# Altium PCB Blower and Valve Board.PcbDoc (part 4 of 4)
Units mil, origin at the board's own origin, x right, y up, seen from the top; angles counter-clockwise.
Board outline 4950 x 3450 mil, 4 copper layers (Top Layer, Signal Layer 1, Signal Layer 2, Bottom Layer), stack 64.4 mil thick; 260 components, 151 nets, 912 pads, 417 vias.
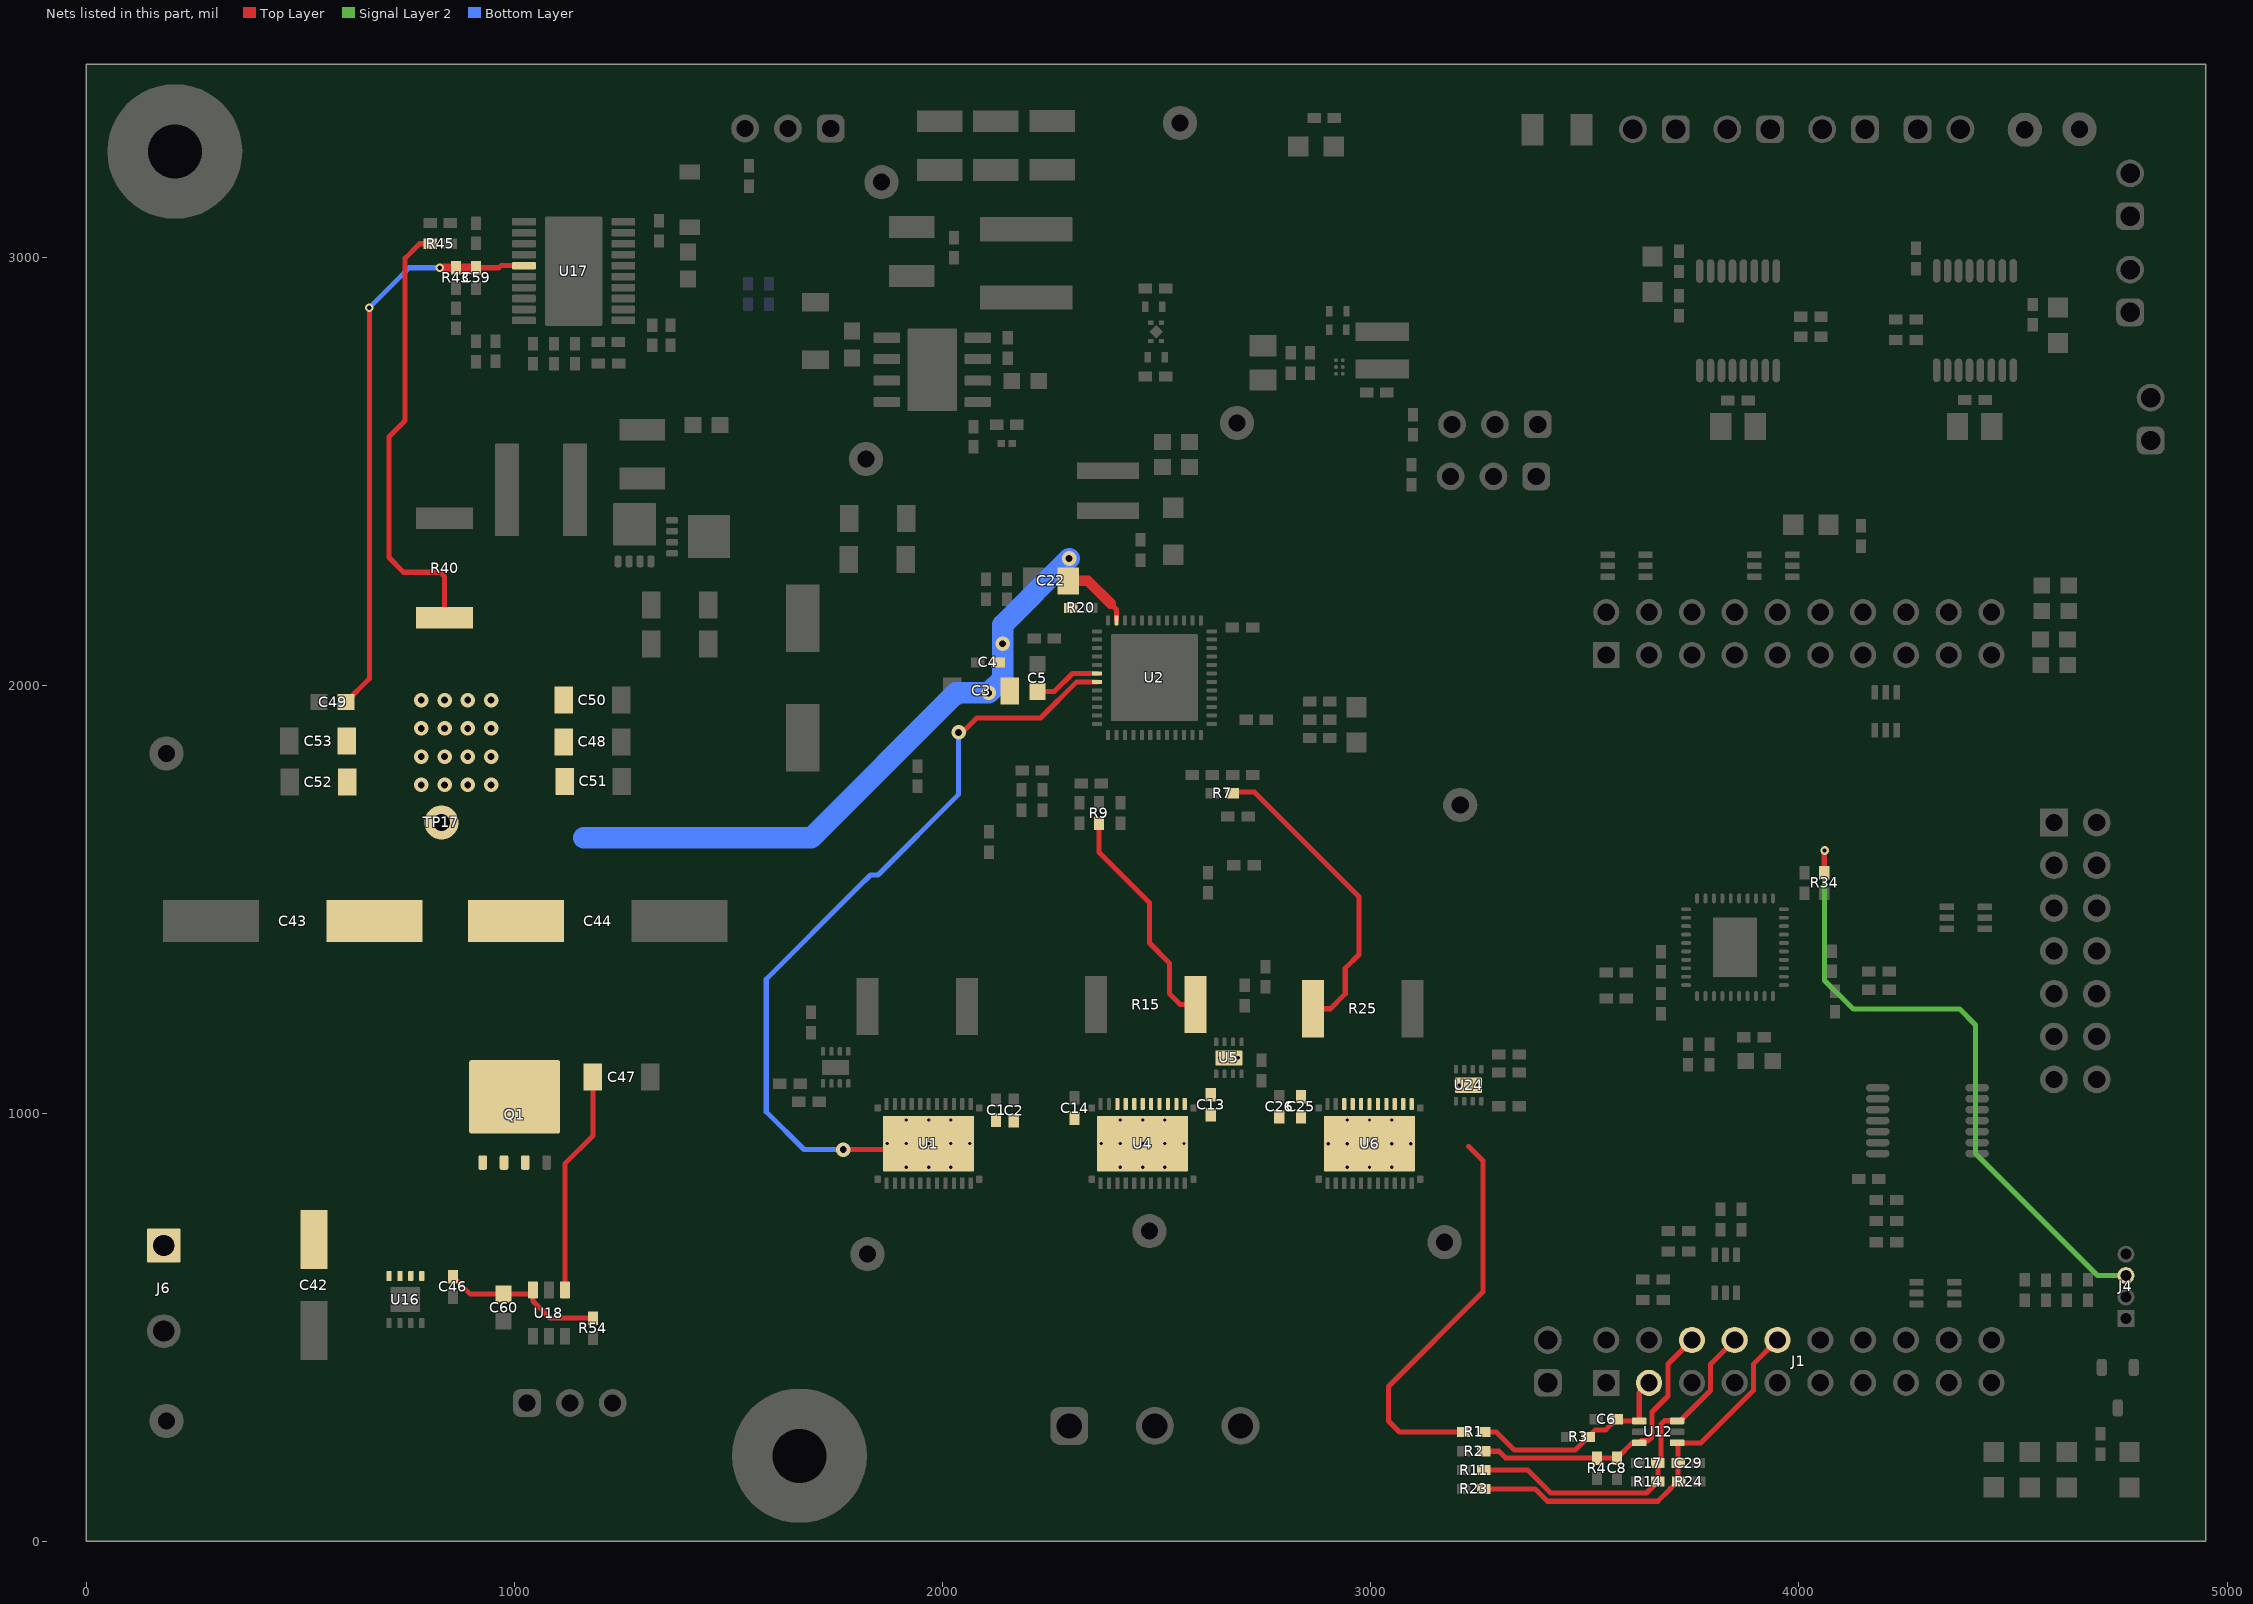
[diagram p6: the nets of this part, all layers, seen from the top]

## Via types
v1: diameter 34, hole 16, Top Layer to Bottom Layer, 186 vias
v2: diameter 20, hole 10, Top Layer to Bottom Layer, 125 vias
v3: diameter 19.68, hole 7.87, Top Layer to Bottom Layer, 94 vias
v4: diameter 19.68, hole 7.87, Top Layer to Bottom Layer, tented both sides, 12 vias

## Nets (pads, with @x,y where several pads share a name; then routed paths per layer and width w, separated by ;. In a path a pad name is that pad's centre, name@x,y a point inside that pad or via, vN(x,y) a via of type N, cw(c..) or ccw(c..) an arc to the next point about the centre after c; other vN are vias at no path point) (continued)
SPB1: C13.2 R9.1 R15.2 U4.12 U4.13 U4.14 U4.15 U4.16 U4.17 U4.18 U4.19 U4.20 U5.9@2668.47,1129.31 | length 538
  Top Layer w12: R9.1@2364.96,1677.65 2364.96,1609.77 2373.86,1600.88 2482.92,1491.81 2482.92,1397.63 2529.53,1351.03 2529.53,1279.7 2555.12,1254.11 R15.2@2590.8,1254.11
  other v3: 2646.82,1129.31 2690.13,1129.31
SPC1: C25.2 R7.1 R25.2 U6.12 U6.13 U6.14 U6.15 U6.16 U6.17 U6.18 U6.19 U6.20 U24.9@3228.35,1065.55 | length 726.8
  Top Layer w12: R7.1@2677.1,1750.51 2727.84,1750.51 2972.44,1505.91 2972.44,1370.71 2940.51,1338.78 2940.51,1279.09 2905.69,1244.27 R25.2@2864.81,1244.27
  other v3: 3206.69,1065.55 3250,1065.55
TXD: J4.3 R34.2 | length 1521
  Top Layer w12: R34.2@4059.11,1561.62 4059.11,1612.89 v2(4060,1613.78)
  Signal Layer 2 w12: v2(4060,1613.78) 4060,1310.41 4127.1,1243.31 4375.45,1243.31 4412.51,1206.25 4412.51,906.16 4697.71,620.97 J4.3@4763.78,620.97
VDRAIN: C1.1 C2.1 C3.1 C4.1 C5.1 C13.1 C14.1 C22.1 C25.1 C26.1 C43.1 C44.1 C47.1 C48.1 C49.1 C50.1 C51.1 C52.1 C53.1 C59.1 Q1.5 Q1.6 Q1.7 Q1.8 Q1.9@1000.49,1038.58 R1.2 R20.2 R40.1 R43.2 R45.2 TP17.1 U1.27 U2.6 U2.7 U2.47 U4.27 U6.27 U17.5 U18.4 | length 7512.7
  Top Layer w12: C49.1@606.78,1960.63 661.01,2014.86 v2(661.01,2881.67) ; R45.2@803.19,3031.03 778.37,3031.03 744.59,2997.25 744.59,2618.11 706.69,2580.22 706.69,2297.93 740.85,2263.78 826.77,2263.78 836.61,2253.94 R40.1@836.61,2157.48 ; C59.1@910.25,2974.84 963.1,2974.84 968.1,2979.85 U17.5@1022.14,2979.85 ; U18.4@1117.64,587.63 1117.64,882.14 1183.07,947.58 C47.1@1183.07,1084.65 ; v1(1767.72,915.35) 1915.21,915.35 1953.22,915.35 v3(1967.18,929.31) ; v1(2037.44,1889.76) 2046.17,1889.76 2079.54,1923.13 2228.49,1923.13 2313.07,2007.71 U2.7@2360.88,2007.71 ; C5.1@2221.11,1985.01 2260.83,1985.01 2303.21,2027.4 U2.6@2360.88,2027.4 ; 2392.37,2190.52 2406.15,2176.74 U2.47@2406.15,2151.41 ; R1.2@3217.13,255.87 3066.78,255.87 3041.34,281.3 3041.34,362.17 3262.41,583.24 3262.41,889.02 3228.94,922.49
  Top Layer w20: v2(825.29,2974.84) R43.2@863.01,2974.84 C59.1@910.25,2974.84
  Top Layer w25: C22.1@2292.96,2243.67 2339.22,2243.67 2392.37,2190.52
  Bottom Layer w12: v2(661.01,2881.67) 754.19,2974.84 v2(825.29,2974.84) ; v1(1767.72,915.35) 1676.32,915.35 1587.96,1003.72 1587.96,1313.18 1800.71,1525.93 1800.71,1526.06 1818.28,1543.63 1818.41,1543.63 1831.52,1556.74 1849.07,1556.74 2037.4,1745.08 2037.4,1881.58 2037.44,1881.62 v1(2037.44,1889.76)
  Bottom Layer w50: 1161.42,1643.7 1693.56,1643.7 2031.92,1982.06 v1(2107.88,1982.06) 2140.16,2014.34 v1(2140.16,2096.67) 2140.16,2140.69 v1(2295.32,2295.85)
  other v1: 782.28,1766.99 836.61,1766.99 890.95,1766.99 945.28,1766.99 782.28,1833.04 836.61,1833.04 890.95,1833.04 945.28,1833.04 782.28,1899.1 836.61,1899.1 890.95,1899.1 945.28,1899.1 782.28,1965.15 836.61,1965.15 890.95,1965.15 945.28,1965.15
  other v3: 1915.21,874.19 1967.18,874.19 2019.14,874.19 2415.21,874.19 2467.18,874.19 2519.14,874.19 2945.08,873.99 2997.05,873.99 3049.02,873.99 1870.72,929.31 1915.21,929.31 2019.14,929.31 2063.63,929.31 2370.72,929.31 2415.21,929.31 2467.18,929.31 2519.14,929.31 2563.63,929.31 2900.59,929.11 2945.08,929.11 2997.05,929.11 3049.02,929.11 3093.51,929.11 1915.21,984.42 1967.18,984.42 2019.14,984.42 2415.21,984.42 2467.18,984.42 2519.14,984.42 2945.08,984.23 2997.05,984.23 3049.02,984.23
VIN: C42.1 C46.1 C60.1 J6.1 Q1.1 Q1.2 Q1.3 R54.2 U16.1 U16.2 U16.3 U16.4 U18.6 | length 390.4
  Top Layer w12: C46.1@856.3,618.11 896.82,577.59 C60.1@974.41,577.59 1032.8,577.59 U18.6@1042.83,587.63 1042.83,561.58 1082.7,521.72 R54.2@1183.21,521.72
VSENA: C8.1 J1.6 R2.1 R4.2 U12.3 | length 684.6
  Top Layer w12: R2.1@3264.37,210.6 3299.24,210.6 3315.15,194.69 R4.2@3528.35,194.69 C8.1@3575,194.69 3610.63,230.32 U12.3@3626.97,230.32 3631.69,235.03 3647.93,235.03 3656.7,243.8 3656.7,302.07 3694.29,339.66 3694.29,414.76 J1.6@3750,470.47
VSENB: C17.1 J1.8 R11.1 R14.2 U12.6 | length 866.4
  Top Layer w12: R11.1@3264.37,166.62 3366.85,166.62 3420.33,113.14 3643.94,113.14 R14.2@3670.75,139.95 C17.1@3670.75,182.88 3677.81,189.94 3677.81,273.77 3685.95,281.91 3715.14,281.91 U12.6@3715.55,281.5 3722.56,281.5 3793.51,352.45 3793.51,413.98 J1.8@3850,470.47
VSENC: C29.1 J1.10 R23.1 R24.2 U12.4 | length 945.1
  Top Layer w12: R23.1@3264.37,122.63 3383.96,122.63 3412.87,93.73 3670.47,93.73 3699.5,122.75 3699.5,123.07 3717.76,141.33 C29.1@3717.76,182.88 3717.76,228.11 U12.4@3715.55,230.32 3771.38,230.32 3893.51,352.45 3893.51,413.98 J1.10@3950,470.47
VSENVM: C6.1 J1.3 R1.1 R3.2 U12.1 | length 509.9
  Top Layer w12: R1.1@3264.37,255.87 3293.14,255.87 3335.31,213.69 3477.47,213.69 R3.2@3507.87,244.09 3524.4,260.62 3548.81,260.62 C6.1@3573.62,285.43 3577.56,281.5 U12.1@3626.97,281.5 3626.97,347.44 J1.3@3650,370.47
pads on no net: H7.0 H8.0 J1.2 J1.5 J1.7 J1.11 J1.17 J1.18 J1.19 J1.20 J2.4 J2.6 J2.8 J2.10 J2.13 J2.16 J3.2 J3.3 J3.5 J3.6 J3.8 J3.10 J3.11 J3.12 J3.13 J3.14 Q1.9@907.08,963.39 Q1.9@948.12,975 Q1.9@948.12,1020.28 Q1.9@948.12,1065.55 Q1.9@1000.49,975 Q1.9@1000.49,1020.28 Q1.9@1000.49,1025.59 Q1.9@1000.49,1065.55 Q1.9@1052.85,975 Q1.9@1052.85,1020.28 Q1.9@1052.85,1065.55 Q1.9@1093.89,963.39 Q2.9A Q2.9B Q2.9C Q2.9D Q3.9A Q3.9B Q3.9C Q3.9D U1. U1.21 U1.23 U1.24 U1.25 U1.26 U3.9@1732.28,1107.09 U3.9@1767.72,1107.09 U4. U4.21 U4.23 U4.24 U4.25 U4.26 U5.9@2650.76,1129.31 U5.9@2686.19,1129.31 U6. U6.21 U6.23 U6.24 U6.25 U6.26 U7.3 U7.6 U7.11 U8.2 U8.13 U8.14 U8.19 U8.20 U8.29 U8.30 U8.31 U8.32 U8.35 U8.36 U8.37 U8.38 U9.5 U10.3 U10.4 U10.5 U11.5 U12.5 U13.3 U13.4 U13.5 U14.1 U14.5 U15.5 U17.1 U17.21@1138.29,2967.06 U19.4 U24.9@3210.63,1065.55 U24.9@3246.06,1065.55

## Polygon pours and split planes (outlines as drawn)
GND on Top Layer "TOP_LAYER_GND_P129" (solid, remove dead copper, pour order 129): 59.06,3405.51 49.21,3395.67 49.21,49.21 59.06,39.37 4881.73,39.37 4891.73,49.37 4891.73,3395.67 4881.89,3405.51
GND on Top Layer "TOP_LAYER_GND_P127" (solid, remove dead copper, pour order 127): 3900.94,1185.4 3894.44,1178.91 3894.44,1163.63 3917.32,1140.75 3917.32,1088.5 3972.36,1033.46 4035.43,1033.46 4045.28,1043.31 4045.28,1140.93 4000.8,1185.4
3.3V on Top Layer "TOP_LAYER_3.3V_P125" (solid, remove dead copper, pour order 125): 3887.13,1039.29 3906.87,1059.03 3906.87,1144.05 3894.44,1156.48 3894.44,1184.1 3879.91,1198.63 3858.81,1198.63 3832.16,1171.98 3832.16,1152.32 3853.95,1130.52 3853.95,1052.85 3867.52,1039.29
GND on Top Layer "TOP_LAYER_GND_P123" (solid, remove dead copper, pour order 123): 1480.31,2976.22 1469.8,2986.74 1450.99,2986.74 1436.69,2972.44 1352.7,2972.44 1342.18,2961.92 1342.18,2927.75 1407.08,2862.84 1462.91,2862.84 1480.32,2880.25
NetC41_2 on Top Layer "TOP_LAYER_NETC41_2_P121" (solid, remove dead copper, pour order 121): 1205.18,2623.05 1205.18,2589.82 1249,2546.01 1420.41,2546.01 1437.01,2562.6 1437.01,2635.7 1420.8,2651.91 1235.11,2651.91
NetC64_1 on Top Layer "TOP_LAYER_NETC64_1_P117" (solid, remove dead copper, pour order 117): 1073.43,2322.82 1075.67,2320.58 1384.5,2320.58 1387.8,2323.88 1387.8,2483.98 1342.25,2529.53 1241.31,2529.53 1174.17,2596.66 1076.93,2596.66 1073.43,2593.16
NetL2_1 on Top Layer "TOP_LAYER_NETL2_1_P115" (solid, remove dead copper, pour order 115): 769.88,2322.83 1050.01,2322.83 1053.15,2325.98 1053.15,2580.22 1044,2589.37 886.61,2589.37 759.84,2462.6 759.84,2331.56
12V on Top Layer "TOP_LAYER_12V_P113" (solid, remove dead copper, pour order 113): 3850.63,2658.2 3831.67,2677.17 3785,2677.17 3731.83,2624 3731.83,2557.54 3759.84,2529.53 3832.66,2529.53 3850.63,2547.5
12V on Top Layer "TOP_LAYER_12V_P111" (solid, remove dead copper, pour order 111): 4403.17,2648.06 4386.23,2665 4315.1,2665 4277.26,2627.16 4277.26,2561.29 4304.5,2534.04 4383.55,2534.04 4403.17,2553.66
3.3V on Top Layer "TOP_LAYER_3.3V_P081" (solid, remove dead copper, pour order 81): 3089.76,2781.74 2957.56,2781.74 2923.23,2816.07 2923.69,2816.54 2923.69,2928.78 2947.67,2952.76 3088.89,2952.76 3123.11,2918.54 3123.11,2814.96
VIN on Top Layer "TOP_LAYER_VIN_P105" (solid, remove dead copper, pour order 105): 1027.12,920.9 62.66,920.9 39.37,897.61 39.37,629.92 66.93,602.36 938.3,602.36 1043.39,707.46 1043.39,905.56
LDO3.3 on Top Layer "TOP_LAYER_LDO3.3_P085" (solid, remove dead copper, pour order 85): 2493.19,2858.45 2517.24,2834.41 2563.68,2834.41 2608.27,2879 2608.27,2947.99 2573.98,2982.28 2506.13,2982.28 2498.82,2974.98 2498.82,2903.27 2493.19,2897.64
4.0V on Top Layer "TOP_LAYER_4.0V_P079" (solid, remove dead copper, pour order 79): 2312.99,2460.63 2535.6,2460.63 2541.94,2466.97 2541.94,2599.79 2562.23,2620.08 2801.72,2620.08 2885.39,2703.75 2885.39,2736.23 2875.56,2746.06 2702.71,2746.06 2554.37,2746.06 2516.16,2784.27 2504.64,2784.27 2504.64,2688.06 2415,2598.43 2312.99,2598.43 2293.31,2578.74 2293.76,2578.29 2293.76,2480.32
NetC21_2 on Top Layer "TOP_LAYER_NETC21_2_P077" (solid, remove dead copper, pour order 77): 2474.39,2315.77 2487.04,2328.42 2487.04,2349.4 2500.85,2363.21 2559.04,2363.21 2576.16,2380.33 2576.16,2449.47 2569.33,2456.3 2308.16,2456.3 2290.18,2438.31 2290.18,2372.94 2314.12,2348.99 2399.91,2348.99 2433.13,2315.77
VDRAIN on Top Layer "TOP_LAYER_VDRAIN_P073" (solid, remove dead copper, pour order 73): 2259.14,2164.2 2322.83,2164.2 2322.83,2192.07 2332.68,2201.92 2358.18,2201.92 2359.33,2200.76 2372.05,2213.48 2372.05,2283.46 2334.89,2320.62 2263.48,2320.62 2249.36,2306.5 2249.36,2218.81 2249.36,2171.08
VDRAIN on Top Layer "TOP_LAYER_VDRAIN_P071" (solid, remove dead copper, pour order 71): 2086.61,1947.29 2226.08,1947.29 2248.45,1969.65 2248.45,2007.87 2239.81,2016.51 2199.13,2016.51 2193.85,2021.79 2193.85,2086.21 2162.76,2117.29 2128.75,2117.29 2105.79,2094.33 2105.79,2041.2 2086.61,2022.02
SPA1 on Top Layer "TOP_LAYER_SPA1_P067" (solid, remove dead copper, pour order 67): 2096.46,1000.43 2103.25,1007.23 2139.76,1007.23 2146.31,1013.78 2146.31,1066.3 2097.75,1114.86 1978.42,1114.86 1929.13,1164.15 1929.13,1334.41 1918.54,1345 1792.4,1345 1771.65,1324.26 1771.65,1171.63 1777.27,1166.01 1796.58,1166.01 1801.18,1161.42 1801.02,1129.31 1714.57,1129.31 1714.57,1085.43 1800.95,1085.43 1811.02,1075.36 1811.02,1014.4 1824.99,1000.43
VDRAIN on Top Layer "TOP_LAYER_VDRAIN_P063" (solid, remove dead copper, pour order 63): 1801.18,960.8 1801.18,976.55 1833.26,1008.63 3206.14,1010.57 3238.19,978.52 3238.19,890.72 3203.76,856.3 1814.96,856.3 1801.18,870.08
SPC1 on Top Layer "TOP_LAYER_SPC1_P059" (solid, remove dead copper, pour order 59): 3132.53,1000.43 2863.25,1000.43 2848.55,1015.13 2821.46,1015.13 2795.28,1041.31 2795.28,1317.15 2853.99,1375.86 2952.76,1375.86 2966.39,1362.23 2966.39,1216.07 3093.5,1088.95 3265.75,1088.95 3265.75,1044.86 3145.72,1044.86 3132.53,1031.67
SPB1 on Top Layer "TOP_LAYER_SPB1_P055" (solid, remove dead copper, pour order 55): 2332.68,1000.43 2585.15,1000.43 2604.58,1019.86 2638.33,1019.86 2647.88,1029.41 2647.88,1058.98 2633.44,1073.43 2618.11,1073.43 2618.11,1106.89 2703.91,1107.09 2703.91,1150.96 2703.29,1151.57 2633.44,1151.57 2633.44,1314.22 2602.66,1345 2487.83,1345 2460.63,1317.8 2460.63,1155.64 2365.24,1060.25 2349.44,1060.25 2332.68,1043.48
no net on Top Layer "TOP_LAYER_NONET_P053" (solid, remove dead copper, pour order 53): 2545.13,1096.46
MOTC on Top Layer "TOP_LAYER_MOTC_P045" (solid, remove dead copper, pour order 45): 2676.6,846.04 2687.01,856.3 3228.35,856.3 3238.19,846.46 3238.19,590.55 2842.33,194.69 2606.07,194.69 2588.58,212.18 2588.58,650.69 2676.6,738.7
MOTA on Top Layer "TOP_LAYER_MOTA_P041" (solid, remove dead copper, pour order 41): 1801.02,856.3 2233.74,856.3 2244.09,845.95 2244.09,797.24 2391.73,649.61 2391.73,210.02 2376.4,194.69 2155.74,194.69 1761.81,588.26 1761.81,832.93
MOTB on Top Layer "TOP_LAYER_MOTB_P039" (solid, remove dead copper, pour order 39): 2657.48,856.3 2666.51,847.27 2666.51,738.7 2578.74,650.93 2578.74,211.17 2562.25,194.69 2420.69,194.69 2403.2,212.18 2403.2,652.89 2251.46,804.63 2251.46,849.24 2258.51,856.3
12V on Top Layer "TOP_LAYER_12V_P035" (solid, remove dead copper, pour order 35): 2312.99,3030.53 1860.24,3030.53 1838.32,3052.45 1838.32,3220.21 1866.14,3248.03 2312.99,3248.03 2342.52,3218.5 2342.52,3061.02
NetC69_2 on Top Layer "TOP_LAYER_NETC69_2_P033" (solid, remove dead copper, pour order 33): 2045.92,2790.14 2235.79,2790.14 2317.7,2872.05 2317.29,2872.45 2317.29,2936.08 2307.73,2945.65 2078.18,2945.65 2045.92,2913.39
14V on Top Layer "TOP_LAYER_14V_P031" (solid, remove dead copper, pour order 31): 1405.39,2409.63 1409.35,2413.59 1456.49,2460.74 1456.49,2630.89 1613.3,2787.7 1901.63,2787.7 1909.45,2779.88 1909.45,2747.93 1899.61,2738.08 1820.8,2738.08 1787.96,2705.25 1787.96,2588.88 1830.84,2546.01 1830.84,2089.96 1787.96,2047.08 1425.76,2047.08 1405.39,2067.45
VDRAIN on Top Layer "TOP_LAYER_VDRAIN_P023" (solid, remove dead copper, pour order 23): 1082.03,934.85 827.78,934.85 542.16,1220.47 542.16,1654.37 580.71,1692.91 580.71,2031.61 763.67,2214.57 924.89,2214.57 1151.57,1987.88 1151.57,1199.19 1214.57,1136.2 1214.57,1014.85 1134.76,935.04
GND on Bottom Layer "BOTTOM_LAYER_GND_P135" (solid, remove dead copper, pour order 135): 59.06,3405.51 49.21,3395.67 49.21,49.21 59.06,39.37 4881.73,39.37 4891.73,49.37 4891.73,3395.67 4881.89,3405.51
12V on Bottom Layer "BOTTOM_LAYER_12V_P109" (solid, remove dead copper, pour order 109): 1866.9,3248.03 1839.08,3220.21 1838.32,3220.21 1838.32,3055.51 1859.51,3034.32 3028.93,3034.32 3563.2,2500.05 4569.5,2500.05 4605.3,2535.86 4605.3,2674.42 4560.97,2718.74 3773.03,2718.74 3243.74,3248.03 2514.1,3248.03
VDRAIN on Bottom Layer "BOTTOM_LAYER_VDRAIN_P089" (solid, remove dead copper, pour order 89): 523.39,2232.8 475.23,2184.64 475.23,973.11 1109.91,338.43 3161.83,338.43 3239.1,415.7 3239.1,943.95 3146.27,1036.78 1719.41,1036.78 1249.1,1507.08 1249.1,2089.45 1105.75,2232.8
GND on Signal Layer 1 "SIGNAL_LAYER_1_GND_P131" (solid, remove dead copper, pour order 131): 59.06,3405.51 49.21,3395.67 49.21,49.21 59.06,39.37 4881.73,39.37 4891.73,49.37 4891.73,3395.67 4881.89,3405.51
GND on Signal Layer 2 "SIGNAL_LAYER_2_GND_P133" (solid, remove dead copper, pour order 133): 59.06,3405.51 49.21,3395.67 49.21,49.21 59.06,39.37 4881.73,39.37 4891.73,49.37 4891.73,3395.67 4881.89,3405.51

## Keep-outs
Keep-Out Layer:
  text ".Layer_Name" at 577,-858.49 h60

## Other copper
Top Layer:
  text ".Layer_Name" at 577,-858.49 h60
Bottom Layer:
  text ".Layer_Name" at 577,-858.49 h60

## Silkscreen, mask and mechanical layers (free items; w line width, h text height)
Top Overlay:
  text "EN: 2-3" at 1523.68,3375.07 h40
  text ".PRJ_Number" at 472.44,2699.17 h90 r270
  text "REV: .PCB_Rev" at 364.17,2679.54 h72.83 r270
  text "EN: 2-3" at 1131.89,226.38 h40
  text "D11 = Alert 3 / D6 = Alert 1 / D7 = Alert 2 / D8 = MCUON" at 4131.4,100.98 h40
  text ".Layer_Name" at 577,-858.49 h60
Bottom Overlay:
  text ".Layer_Name" at 577,-858.49 h60
Top Paste:
  text ".Layer_Name" at 577,-858.49 h60
Bottom Paste:
  text ".Layer_Name" at 577,-858.49 h60
Top Solder:
  text ".Layer_Name" at 577,-858.49 h60
  text ".Layer_Name" at 577,-858.49 h60
Bottom Solder:
  text ".Layer_Name" at 577,-858.49 h60
Drill Guide:
  text ".Layer_Name" at 577,-858.49 h60
M1 Board Outline:
  the board outline again, w10
  text ".Layer_Name" at 577,-858.49 h60
M2 Board Dimensions:
  rectangle: 0,-275 125,-150
  rectangle: 125,-400 500,-275
  lines w7: 0,-275 1000,-275 ; 125,-400 125,-150 ; 250,-400 250,-150 ; 500,-400 500,-150 ; 750,-400 750,-150 ; 0,-400 1000,-400 1000,-150 0,-150 0,-400
  text ".Layer_Name" at 577,-858.49 h60
M3 3D STEP Top:
  text ".Layer_Name" at 577,-858.49 h60
M4 3D STEP Bottom:
  text ".Layer_Name" at 577,-858.49 h60
M5 Assembly Top:
  lines w10: -292,-930.17 6308,-930.17 ; -292,-726.83 6310,-726.83 ; -292,-523.5 -292,-1133.5 3713,-1133.5 6310,-1133.5 6310,-523.5 -291.5,-523.5 -291.5,-1133.5 1284,-1133.5 ; 2173,-1133.5 2173,-523.5 ; 3440,-726.83 3440,-523.5 ; 4280,-726.83 4280,-523.5 ; 4902,-1140 4902,-937.17
  text "COMPONENTS MARKED 'DNP' SHOULD NOT BE POPULATED." at 1153.5,-318.5 h60
  text "ASSEMBLY VARIANT:" at 1153,-434 h60
  text ".VariantName" at 2189,-434 h60
  text "PCB VIEWED FROM TOP SIDE" at -228.5,-655.67 h60
  text "BOARD #:" at 2248,-655.67 h60
  text ".PRJ_Number" at 2793.5,-655.67 h60
  text "REV:" at 3638,-655.67 h60
  text ".PCB_Rev" at 3929.5,-655.67 h60
  text "SVN REV:" at 4476,-655.67 h60
  text ".VersionControl_RevNumber" at 4982,-655.67 h60
  text "TID #:" at 2248,-859 h60
  text ".TID" at 2793.5,-859 h60
  text "PLOT NAME =" at -228.5,-1064.34 h60
  text ".plot_File_Name" at 577,-1064.34 h60
  text "GENERATED    :" at 2250,-1064.34 h60
  text ".Print_Date" at 3119.5,-1064.34 h60
  text ".Print_Time" at 3848.5,-1064.34 h60
  text "TEXAS INSTRUMENTS" at 5113,-1064.34 h60
M6 Assembly Bottom:
  lines w10: -292.5,-727.33 6309.5,-727.33 ; -290.5,-930.67 6309.5,-930.67 ; 1115.5,-1140.5 1115.5,-937.67 ; 1737.5,-727.33 1737.5,-524 ; 2577.5,-727.33 2577.5,-524 ; 3844.5,-1134 3844.5,-524 ; 4733.5,-1134 6309,-1134 6309,-524 -292.5,-524 -292.5,-1134 2304.5,-1134 6309.5,-1134 6309.5,-524
  text "COMPONENTS MARKED 'DNP' SHOULD NOT BE POPULATED." at 6102,-318 h60
  text ".VariantName" at 5058,-434 h60
  text "ASSEMBLY VARIANT:" at 6097,-434 h60
  text ".VersionControl_RevNumber" at 1035.5,-656.17 h60
  text "SVN REV:" at 1541.5,-656.17 h60
  text ".PCB_Rev" at 2088,-656.17 h60
  text "REV:" at 2379.5,-656.17 h60
  text ".PRJ_Number" at 3224,-656.17 h60
  text "BOARD #:" at 3769.5,-656.17 h60
  text "PCB VIEWED FROM BOTTOM SIDE" at 6246,-656.17 h60
  text ".TID" at 3224,-859.5 h60
  text "TID #:" at 3769.5,-859.5 h60
  text "TEXAS INSTRUMENTS" at 904.5,-1064.84 h60
  text ".Print_Time" at 2169,-1064.84 h60
  text ".Print_Date" at 2898,-1064.84 h60
  text "GENERATED    :" at 3767.5,-1064.84 h60
  text ".plot_File_Name" at 5440.5,-1064.84 h60
  text "PLOT NAME =" at 6246,-1064.84 h60
M9 Title Sheet:
  drawing of 57 lines, arcs and shapes, not listed
  text "1" at 739.84,8036.5 h70
  text "2" at 3235.5,8036.5 h70
  text "3" at 5724.84,8036.5 h70
  text "4" at 8231.51,8036.5 h70
  text "5" at 10730.5,8036.5 h70
  text "6" at 13235.5,8036.5 h70
  text "A" at -416.5,6893.5 h70
  text "A" at 14383.5,6893.5 h70
  text "B" at -416.5,4513.5 h70
  text "B" at 14383.5,4513.5 h70
  text "C" at -416.5,2138.5 h70
  text "C" at 14383.5,2138.5 h70
  text "PROJECT TITLE:" at 11343.5,277.5 h45
  text ".PRJ_Title" at 11393.5,144.17 h70
  text "DESIGNED FOR:" at 11343.5,-23.5 h45
  text ".PRJ_Customer" at 11393.5,-163.5 h70
  text "D" at -416.5,-231.5 h70
  text "D" at 14383.5,-231.5 h70
  text "FILE NAME:" at 11343.5,-323.5 h45
  text ".PCB_File_Name_No_Path" at 11393.5,-443.5 h70
  text "Texas Instruments (TI) and/or its licensors do not warrant the accuracy or completeness of this specification" at 6374,-605.34 h45
  text "ENGINEER:" at 11343.5,-613.5 h45
  text "LAYOUT BY:" at 12848.5,-613.5 h45
  text "or any information contained therein. TI and/or its licensors do not warrant that this design will meet" at 6329.01,-718 h45
  text ".PRJ_Engineer" at 11393.5,-768.49 h70
  text ".PCB_Layout" at 12899,-768.49 h70
  text "the specifications, will be suitable for your application or fit for any particular purpose, or will operate in" at 6329.01,-830.67 h45
  text ".Layer_Name" at 577,-858.49 h60
  text "ALTIUM DESIGNER VERSION:" at 12848.5,-923.5 h45
  text "an implementation. TI and/or its licensors do not warrant that the design is production worthy. You should" at 6329.01,-943.33 h45
  text "completely validate and test your design implementation to confirm the system functionality for your application." at 6374,-1056 h45
  text ".print_Scale" at 11393.5,-1056.83 h70
  text ".Application_BuildNumber" at 12899,-1056.83 h70
  text "1" at 739.84,-1263.5 h70
  text "2" at 3235.5,-1263.5 h70
  text "3" at 5724.84,-1263.5 h70
  text "4" at 8231.51,-1263.5 h70
  text "5" at 10730.5,-1263.5 h70
  text "6" at 13235.5,-1263.5 h70
M10 Fab Notes:
  drawing of 189 lines, arcs and shapes, not listed
  text "DESIGN INFORMATION" at 12382.02,6356.17 h60
  text "MIN. TRACK WIDTH:" at 11737.46,6224.05 h60
  text "8" at 12833.7,6224.05 h60
  text "MIL" at 12988.46,6224.05 h60
  text "MIN. CLEARANCE:" at 11737.46,6099.92 h60
  text "0.2" at 12773.7,6099.93 h60
  text "mm" at 12988.46,6099.92 h60
  text "MIN. VIA PAD SIZE:" at 11737.46,5975.8 h60
  text "24" at 12803.71,5975.8 h60
  text "MIL" at 12988.46,5975.8 h60
  text "0.05mm (2MIL)" at 12432.46,5845.9 h60
  text "MINIMUM ANNULAR RING" at 11408.23,5837.67 h60
  text "EXTERNAL" at 13140.46,5837.67 h60
  text "PER" at 11608.23,5727.55 h60
  text "IPC-D-275 CLASS 2 LEVEL C" at 11828.23,5727.54 h60
  text "MIL, HOLES" at 13316.46,5627.07 h60
  text "+/-" at 12924,5618.48 h60
  text "+/-" at 13778,5618.48 h60
  text "REGISTRATION TOLERANCES:" at 11408.23,5617.42 h60
  text "METAL" at 12608,5617.42 h60
  text "5" at 13184.2,5617.42 h60
  text "3" at 14017.2,5617.42 h60
  text "MIL" at 14133.46,5617.42 h60
  text "HOLE SIZE TOLERANCE (UNLESS OTHERWISE SPECIFIED):" at 11408.23,5519.1 h60
  text "+/-" at 13778,5516.23 h60
  text "3" at 14017.2,5515.17 h60
  text "MIL" at 14133.46,5515.17 h60
  text "MATERIAL:" at 11333.46,5377.52 h60
  text "FR-4 High Tg" at 12319.9,5249 h60
  text "X" at 12175.46,5241.01 h60
  text "FR-408" at 11754.46,5236.49 h60
  text "OTHER" at 13242.46,5236.49 h60
  text "62 MIL (1.6mm) +/-10%" at 12074.56,5093.46 h60
  text "X" at 11954.46,5091.01 h60
  text "THICKNESS:" at 11408.23,5085.24 h60
  text "OTHER" at 13359.46,5085.24 h60
  text "TOLERANCE:" at 11408.23,4946.92 h60
  text "X" at 12256.46,4946.92 h60
  text "ANSI IPC-6012 TYPE 3 CLASS 2" at 12434.48,4946.92 h60
  text "OTHER +/-" at 12434.46,4802.73 h60
  text "BOW & TWIST:" at 11408.23,4657.54 h60
  text "X" at 12256.46,4657.54 h60
  text "ANSI IPC-6012 TYPE 3 CLASS 2" at 12434.48,4657.54 h60
  text "OTHER +/-" at 12434.46,4510.85 h60
  text "DRILLING:" at 11333.46,4380.23 h60
  text "NC_DRILL FILES" at 13094.46,4275.04 h60
  text "REFERENCE:" at 11408.23,4271.1 h60
  text "X" at 12065.46,4271.01 h60
  text "AS SHOWN" at 12243.46,4271.1 h60
  text "X" at 12966.46,4271.1 h60
  text "OTHER" at 13392.46,4128.85 h60
  text "PTH COPPER THICKNESS:" at 11407.91,4125.32 h60
  text "X" at 12547.14,4125.32 h60
  text "20-30 um" at 12675.14,4125.32 h60
  text "BOARD FINISH:" at 11333.46,3977.73 h60
  text "SILKSCREEN:" at 11488.68,3867.6 h60
  text "X" at 12446.46,3867.6 h60
  text "TOP" at 12563.46,3867.6 h60
  text "X" at 12956.46,3867.6 h60
  text "BOTTOM" at 13074.46,3867.6 h60
  text "SILKSCREEN COLOR:" at 11488.68,3712.41 h60
  text "X" at 12445.46,3712.41 h60
  text "WHITE" at 12563.46,3712.41 h60
  text "OTHER" at 13074.46,3712.41 h60
  text "X" at 12576.46,3568.96 h60
  text "GREEN" at 12694.46,3568.96 h60
  text "OTHER" at 13312.46,3568.96 h60
  text "SOLDER RESIST COLOR:" at 11488.68,3562.1 h60
  text "X" at 12576.46,3414.71 h60
  text "MATTE" at 12694.46,3414.71 h60
  text "SEMI-GLOSS" at 13312,3414.07 h60
  text "IMMERSION GOLD (ENIG)" at 12394.46,3241.94 h60
  text "ENEPIG" at 13732,3234.72 h60
  text "SURFACE FINISH:" at 11333.46,3233.72 h60
  text "X" at 12216.46,3233.72 h60
  text "IMM. TIN/SILVER OR EQUIV" at 11663,3096.4 h60
  text "OTHER" at 13094.46,3092.47 h60
  text "ARRAY/PANEL:" at 11333.46,2937.09 h60
  text "CUT AND TRIM PER M1 BOARD OUTLINE" at 12394.46,2928.87 h60
  text "N.C. ROUTE" at 12394.46,2792.9 h60
  text "X" at 13082.46,2792.9 h60
  text "V. SCORE" at 13260.46,2792.9 h60
  text "CERTIFICATION:" at 11333.46,2663.77 h60
  text "MATERIALS AND WORKMANSHIP FOR ALL PCBS" at 12058.46,2663.77 h60
  text "TO MEET OR EXCEED THE REQUIREMENTS OF:" at 12058.46,2569.71 h60
  text "X" at 11695.97,2441.08 h60
  text "ANSI IPC-A-600F CLASS ->" at 11823.96,2441.08 h60
  text "X" at 13471.97,2441.08 h60
  text "2" at 13581.96,2441.08 h60
  text "1" at 13266.96,2439.58 h60
  text "3" at 13935.96,2439.58 h60
  text "X" at 12507.97,2293.39 h60
  text "RoHS" at 12635.96,2293.39 h60
  text "OTHER" at 13280.36,2293.39 h60
  text "PER ORDER" at 13677.42,2293.39 h60
  text "ALL BOARDS MUST MEET OR EXCEED UL94-V0 REQUIREMENTS." at 11361,2139.57 h60
  text "PCB MUST BEAR THE UL94V-0 UL REGISTERED MATERIAL ID NUMBER" at 11361,2023.5 h60
  text "ADDITIONAL REQUIREMENTS:" at 11333.46,1854.08 h60
  text "MICROSECTION:" at 11408.23,1746.95 h60
  text "YES" at 12313.96,1746.95 h60
  text "REQUIRED" at 13175.46,1602.62 h60
  text "BARE BOARD ELEC. TEST:" at 11408.23,1599.76 h60
  text "NONE" at 12713.96,1599.76 h60
  text "X" at 13057.46,1599.76 h60
  text "PER ORDER" at 13767.46,1599.76 h60
  text "XX MIL VIAS REQUIRE NON-CONDUCTIVE FILL AND PLANARIZE" at 11576.38,1394.82 h59
  text "XX MIL VIAS REQUIRE CONDUCTIVE FILL AND PLANARIZE" at 11584.38,1290.84 h60
  text "OUTER XX MIL TRACES REQUIRE 50 OHM SINGLE-ENDED IMPEDANCE" at 11583.39,1127.46 h58
  text "LAYER 2 & 3 (INNER LAYERS) XX MIL WIDE, XX MIL SPACE / TRACES REQUIRE 100 OHM DIFFERENTIAL IMPEDANCE" at 11575.39,891.74 h60
  text ".Layer_Name" at 577,-858.49 h60
M11 Gerber Information:
  lines w10: -292,-930.17 6308,-930.17 ; -292,-726.83 6310,-726.83 ; -292,-523.5 -292,-1133.5 3713,-1133.5 6310,-1133.5 6310,-523.5 -291.5,-523.5 -291.5,-1133.5 1284,-1133.5 ; 2173,-1133.5 2173,-523.5 ; 3440,-726.83 3440,-523.5 ; 4280,-726.83 4280,-523.5 ; 4902,-1140 4902,-937.17
  text "ALL ARTWORK VIEWED FROM TOP SIDE" at -228.5,-655.67 h60
  text "BOARD #:" at 2248,-655.67 h60
  text ".PRJ_Number" at 2793.5,-655.67 h60
  text "REV:" at 3638,-655.67 h60
  text ".PCB_Rev" at 3929.5,-655.67 h60
  text "SVN REV:" at 4476,-655.67 h60
  text ".VersionControl_RevNumber" at 4982,-655.67 h60
  text "LAYER NAME =" at -228.5,-858.49 h60
  text "TID #:" at 2248,-859 h60
  text ".TID" at 2793.5,-859 h60
  text "PLOT NAME =" at -228.5,-1064.34 h60
  text ".plot_File_Name" at 577,-1064.34 h60
  text "GENERATED    :" at 2250,-1064.34 h60
  text ".Print_Date" at 3119.5,-1064.34 h60
  text ".Print_Time" at 3848.5,-1064.34 h60
  text "TEXAS INSTRUMENTS" at 5113,-1064.34 h60
M12 Stackup:
  drawing of 295 lines, arcs and shapes, not listed
  text "Layer" at 9811.59,7289.94 h60
  text "Name" at 10221.51,7289.94 h60
  text "Material" at 11161.25,7289.94 h60
  text "Thickness" at 12021.02,7289.94 h60
  text "Constant" at 12670.85,7289.94 h60
  text "Board Layer Stack" at 13240.71,7289.94 h60
  text "1" at 9811.59,7169.94 h60
  text "Top Overlay" at 10221.51,7169.94 h60
  text "2" at 9811.59,7049.94 h60
  text "Top Solder" at 10221.51,7049.94 h60
  text "Solder Resist" at 11161.25,7049.94 h60
  text "0.40mil" at 12021.02,7049.94 h60
  text "3.5" at 12670.85,7049.94 h60
  text "3" at 9811.59,6929.94 h60
  text "Top Layer" at 10221.51,6929.94 h60
  text "Copper" at 11161.25,6929.94 h60
  text "2.80mil" at 12021.02,6929.94 h60
  text "4" at 9811.59,6809.94 h60
  text "Dielectric 1" at 10221.51,6809.94 h60
  text "FR-4" at 11161.25,6809.94 h60
  text "8.00mil" at 12021.02,6809.94 h60
  text "4.2" at 12670.85,6809.94 h60
  text "5" at 9811.59,6689.94 h60
  text "Signal Layer 1" at 10221.51,6689.94 h60
  text "Copper" at 11161.25,6689.94 h60
  text "1.40mil" at 12021.02,6689.94 h60
  text "6" at 9811.59,6569.94 h60
  text "Dielectric 2" at 10221.51,6569.94 h60
  text "FR-4" at 11161.25,6569.94 h60
  text "40.00mil" at 12021.02,6569.94 h60
  text "4.2" at 12670.85,6569.94 h60
  text "7" at 9811.59,6449.94 h60
  text "Signal Layer 2" at 10221.51,6449.94 h60
  text "Copper" at 11161.25,6449.94 h60
  text "1.40mil" at 12021.02,6449.94 h60
  text "8" at 9811.59,6329.94 h60
  text "Dielectric 3" at 10221.51,6329.94 h60
  text "FR-4" at 11161.25,6329.94 h60
  text "8.00mil" at 12021.02,6329.94 h60
  text "4.2" at 12670.85,6329.94 h60
  text "9" at 9811.59,6209.94 h60
  text "Bottom Layer" at 10221.51,6209.94 h60
  text "Copper" at 11161.25,6209.94 h60
  text "2.80mil" at 12021.02,6209.94 h60
  text "10" at 9811.59,6089.94 h60
  text "Bottom Solder" at 10221.51,6089.94 h60
  text "Solder Resist" at 11161.25,6089.94 h60
  text "0.40mil" at 12021.02,6089.94 h60
  text "3.5" at 12670.85,6089.94 h60
  text "11" at 9811.59,5969.94 h60
  text "Bottom Overlay" at 10221.51,5969.94 h60
  text ".Layer_Name" at 577,-858.49 h60
M13 Component Bodies Top:
  text ".Layer_Name" at 577,-858.49 h60
M14 Component Bodies Bottom:
  text ".Layer_Name" at 577,-858.49 h60
M15 Courtyards Top:
  text ".Layer_Name" at 577,-858.49 h60
M16 Courtyards Bottom:
  text ".Layer_Name" at 577,-858.49 h60
Drill Drawing:
  circle w10: c5363.72,3327.96 r16.58
  circle w10: c5363.72,3327.96 r27.63
  circle w10: c5363.72,2333.4 r27.63
  lines w10: 5336.09,2457.72 5363.72,2430.1 5391.34,2457.72 5363.72,2485.35 5336.09,2457.72 ; 5336.09,2568.23 5349.9,2568.23 5363.72,2554.42 5377.53,2568.23 5391.34,2568.23 5377.53,2582.04 5391.34,2595.86 5377.53,2595.86 5363.72,2609.67 5349.9,2595.86 5336.09,2595.86 5349.9,2582.04 5336.09,2568.23 ; 5336.09,2678.74 5391.34,2678.74 5391.34,2733.99 5336.09,2733.99 5336.09,2678.74 ; 5336.09,2803.06 5363.72,2816.87 5391.34,2803.06 5377.53,2830.68 5391.34,2858.31 5363.72,2844.5 5336.09,2858.31 5349.9,2830.68 5336.09,2803.06 ; 5336.09,2941.19 5349.9,2941.19 5349.9,2927.38 5377.53,2927.38 5377.53,2941.19 5391.34,2941.19 5391.34,2968.82 5377.53,2968.82 5377.53,2982.63 5349.9,2982.63 5349.9,2968.82 5336.09,2968.82 5336.09,2941.19 ; 5336.09,3051.7 5336.09,3065.51 5349.9,3079.32 5336.09,3093.14 5336.09,3106.95 5349.9,3106.95 5363.72,3093.14 5377.53,3106.95 5391.34,3106.95 5391.34,3093.14 5377.53,3079.32 5391.34,3065.51 5391.34,3051.7 5377.53,3051.7 5363.72,3065.51 5349.9,3051.7 5336.09,3051.7 ; 5336.09,3231.27 5391.34,3231.27 5363.72,3176.02 5336.09,3231.27 ; 5336.09,3424.66 5391.34,3424.66 5391.34,3479.91 5336.09,3479.91 5336.09,3424.66 ; 5347.14,3220.22 5380.29,3220.22 5363.72,3187.07 5347.14,3220.22 ; 5347.14,3435.71 5380.29,3435.71 5380.29,3468.86 5347.14,3468.86 5347.14,3435.71
  lines w12: 5286,2268.48 8517.49,2268.48 ; 5286,3511.68 8517.49,3511.68 ; 5623.86,2144.16 5623.86,3636 ; 5955.86,2144.16 5955.86,3636 ; 6592.43,2144.16 6592.43,3636 ; 6851.57,2144.16 6851.57,3636 ; 7226.72,2144.16 7226.72,3636 ; 7951.05,2144.16 7951.05,3636 ; 5286,2144.16 8517.49,2144.16 8517.49,3636 5286,3636 5286,2144.16
  text "Symbol" at 5360.59,3548.98 h72
  text "Quantity" at 5661.16,3548.98 h72
  text "Finished Hole Size" at 5993.16,3548.98 h72
  text "Plated" at 6629.72,3548.98 h72
  text "Hole Type" at 6888.86,3548.98 h72
  text "Drill Layer Pair" at 7264.02,3548.98 h72
  text "Hole Tolerance" at 7988.35,3548.98 h72
  text "106" at 5661.16,3424.66 h60
  text "7.87mil (0.200mm)" at 5993.16,3424.66 h60
  text "PTH" at 6629.72,3424.66 h60
  text "Round" at 6888.86,3424.66 h60
  text "Top Layer - Bottom Layer" at 7264.02,3424.66 h60
  text "125" at 5661.16,3300.34 h60
  text "10.00mil (0.254mm)" at 5993.16,3300.34 h60
  text "PTH" at 6629.72,3300.34 h60
  text "Round" at 6888.86,3300.34 h60
  text "Top Layer - Bottom Layer" at 7264.02,3300.34 h60
  text "186" at 5661.16,3176.02 h60
  text "16.00mil (0.406mm)" at 5993.16,3176.02 h60
  text "PTH" at 6629.72,3176.02 h60
  text "Round" at 6888.86,3176.02 h60
  text "Top Layer - Bottom Layer" at 7264.02,3176.02 h60
  text "4" at 5661.16,3051.7 h60
  text "25.59mil (0.650mm)" at 5993.16,3051.7 h60
  text "PTH" at 6629.72,3051.7 h60
  text "Round" at 6888.86,3051.7 h60
  text "Top Layer - Bottom Layer" at 7264.02,3051.7 h60
  text "39" at 5661.16,2927.38 h60
  text "40.00mil (1.016mm)" at 5993.16,2927.38 h60
  text "PTH" at 6629.72,2927.38 h60
  text "Round" at 6888.86,2927.38 h60
  text "Top Layer - Bottom Layer" at 7264.02,2927.38 h60
  text "40" at 5661.16,2803.06 h60
  text "40.16mil (1.020mm)" at 5993.16,2803.06 h60
  text "PTH" at 6629.72,2803.06 h60
  text "Round" at 6888.86,2803.06 h60
  text "Top Layer - Bottom Layer" at 7264.02,2803.06 h60
  text "16" at 5661.16,2678.74 h60
  text "45.28mil (1.150mm)" at 5993.16,2678.74 h60
  text "PTH" at 6629.72,2678.74 h60
  text "Round" at 6888.86,2678.74 h60
  text "Top Layer - Bottom Layer" at 7264.02,2678.74 h60
  text "2" at 5661.16,2554.42 h60
  text "49.21mil (1.250mm)" at 5993.16,2554.42 h60
  text "PTH" at 6629.72,2554.42 h60
  text "Round" at 6888.86,2554.42 h60
  text "Top Layer - Bottom Layer" at 7264.02,2554.42 h60
  text "3" at 5661.16,2430.1 h60
  text "59.06mil (1.500mm)" at 5993.16,2430.1 h60
  text "PTH" at 6629.72,2430.1 h60
  text "Round" at 6888.86,2430.1 h60
  text "Top Layer - Bottom Layer" at 7264.02,2430.1 h60
  text "2" at 5661.16,2305.78 h60
  text "125.98mil (3.200mm)" at 5993.16,2305.78 h60
  text "PTH" at 6629.72,2305.78 h60
  text "Round" at 6888.86,2305.78 h60
  text "Top Layer - Bottom Layer" at 7264.02,2305.78 h60
  text "523 Total" at 5661.16,2181.46 h60
  text ".Layer_Name" at 577,-858.49 h60
Mechanical 17:
  text ".Layer_Name" at 577,-858.49 h60
Mechanical 18:
  text ".Layer_Name" at 577,-858.49 h60
Mechanical 19:
  text ".Layer_Name" at 577,-858.49 h60

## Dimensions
0,-400 to 1000,-400 on M2 Board Dimensions
0,0 to 0,3450 on M2 Board Dimensions
0,0 to 4950,0 on M2 Board Dimensions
